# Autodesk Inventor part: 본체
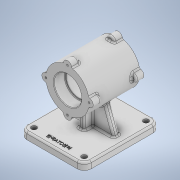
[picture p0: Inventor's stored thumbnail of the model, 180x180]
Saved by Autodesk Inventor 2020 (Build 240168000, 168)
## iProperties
Created: 2022-11
Part Number: 본체
Material: 일반
Document SubType Name: Modeling
Designer: owner
Density: 1 g/cm^3
Appearance: 기본값
Mass: 448.497 g
Surface Area: 803.898 cm^2
Volume: 448.497 cm^3
Author: owner
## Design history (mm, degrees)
sketch "스케치1"
  geometry: L1 (55, 65)-(-55, 65); L2 (-55, 65)-(-55, -65); L3 (-55, -65)-(55, -65); L4 (55, -65)-(55, 65); L5 (55, 65)-(-55, -65); L6 (-55, 65)-(55, -65); 1 further point
  constraints: 12 end point, 2 midpoint, 2 parallel, 1 horizontal, 1 perpendicular
  dimensions: "d0" = 110 distance of L3.end L2.end; "d1" = 130 distance of L2.end L1.end
extrude "돌출1" new body sketch "스케치1" distance "d2" = 12; taper "d3" = 0 deg
node "작업 평면1"
sketch "스케치6"
  geometry: L1 (0, 0)-(110, 0) reference; C1 r 37 at (55, 82); 2 further points
  constraints: 1 centre point, 1 midpoint, 1 vertical alignment
  dimensions: "d20" = 82 distance from line of L1 C1.centre; "d86" = 74 diameter of C1
extrude "돌출4" join sketch "스케치6" stored distance "d21" = 87; taper "d22" = 0 deg
sketch "스케치7"
  geometry: L1 (80.336, 55.036)-(96, 12); L2 (0, 12)-(110, 12) reference; L3 (110, 0)-(110, 12) reference; L4 (29.664, 55.036)-(14, 12); L5 (0, 0)-(0, 12) reference; A1 r 37 centre (55, 82) between (80.336, 55.036) and (29.664, 55.036) reference; 3 further points
  constraints: 4 end point, 2 point on circle
  dimensions: "d23" = 70 deg angle of L2 L1; "d24" = 0 distance from line of L2 L1.end; "d25" = 14 distance from line of L3 L1.end; "d26" = 70 deg angle of L2 L4; "d27" = 14 distance from line of L5 L4.end; "d28" = 0 distance from line of L2 L4.end
extrude "돌출5" join sketch "스케치7" stored distance "d29" = 10; taper "d30" = 0 deg
sketch "스케치9"
  geometry: L1 (14, 12)-(96, 12) reference; L2 (60, 52)-(50, 52); L3 (50, 52)-(50, 12); L4 (50, 12)-(60, 12); L5 (60, 12)-(60, 52); L6 (60, 52)-(50, 12); L7 (50, 52)-(60, 12); A1 r 37 centre (55, 82) between (29.664, 55.036) and (80.336, 55.036) reference; 5 further points
  constraints: 12 end point, 3 midpoint, 2 parallel, 1 horizontal, 1 perpendicular, 1 vertical alignment
  dimensions: "d31" = 10 distance of L4.end L3.end; "d32" = 40 distance of L3.end L2.end; "d33" = 0 distance between parallel lines of L4 L1
extrude "돌출6" join sketch "스케치9" stored distance "d34" = 40; taper "d35" = 0 deg
sketch "스케치10"
  geometry: C1 r 7 at (0, 37); 2 further points
  constraints: 2 vertical alignment, 1 centre point, 1 other
  dimensions: "d36" = 14 diameter of C1
extrude "돌출7" join sketch "스케치10" distance "d37" = 14; taper "d38" = 0 deg
sketch "스케치11"
  geometry: A1 r 7 centre (55, 119) between (61.969, 118.338) and (48.031, 118.338) reference; 2 further points
  constraints: 1 coincident
hole "구멍1" sketch "스케치11" at (55, 119) diameter "d39" = 3.242; stored, may be unused: countersink angle "d43" = 90 deg, drill point angle "d45" = 118 deg; dims "d40" = 8, "d41" = 4, "d42" = 2, "d44" = 11.8
fillet "모깎기4" dims "d76" = 3
fillet "모깎기5" dims "d77" = 3
sketch "스케치12"
  geometry: A1 r 37 centre (55, 82) between (48.031, 118.338) and (18.662, 88.969) reference; 2 further points
  constraints: 1 coincident
hole "구멍2" sketch "스케치12" at (55, 82) diameter "d49" = 47; stored, may be unused: countersink angle "d53" = 90 deg, drill point angle "d55" = 0 deg; dims "d50" = 8, "d51" = 4, "d52" = 2, "d54" = 19
sketch "스케치13"
  geometry: C1 r 23.5 at (0, 0) reference; 2 further points
  constraints: 1 coincident
hole "구멍3" sketch "스케치13" at (0, 0) diameter "d56" = 42; stored, may be unused: countersink angle "d60" = 90 deg, drill point angle "d62" = 0 deg; dims "d57" = 8, "d58" = 4, "d59" = 2, "d61" = 19
fillet "모깎기1" dims "d63" = 12
sketch "스케치14"
  geometry: A1 r 12 centre (-43, -53) between (-55, -53) and (-43, -65) reference; 2 further points
  constraints: 1 coincident
hole "구멍4" sketch "스케치14" at (-43, -53) diameter "d64" = 9; stored, may be unused: countersink angle "d68" = 90 deg, drill point angle "d70" = 0 deg; dims "d65" = 8, "d66" = 4, "d67" = 2, "d69" = 19
fillet "모깎기2" dims "d71" = 3
fillet "모깎기3" dims "d72" = 1
chamfer "모따기1" distance "d73" = 1; stored, may be unused: second distance "d74" = 2, angle "d75" = 45 deg
fillet "모깎기6" dims "d78" = 3
fillet "모깎기7" dims "d79" = 3
fillet "모깎기8" dims "d80" = 3
fillet "모깎기9" dims "d81" = 3
fillet "모깎기10" dims "d82" = 3
sketch "스케치15"
  geometry: L1 (-55, -53)-(-52, -53) reference; L2 (43, -62)-(-43, -62) reference; 3 further points
  constraints: 1 midpoint, 1 vertical alignment, 1 other
  dimensions: "d83" = 0 distance from line of point (0, -53) L1
feature "엠보싱1" sketch "스케치15" dims "d0" = 110, "d1" = 130, "d24" = 0, "d84" = 0.5, "d85" = 0
sketch "스케치16"
  geometry: 1 further point
node "솔리드1"
pattern_circular "원형 패턴1" dims angle "d47" = 360 deg
mirror "미러1"
mirror "미러2"
mirror "미러3"
feature "A9D066F2-1C7D-4E18-AEED-F7BC21143FA4" dims "d39" = 3.242, "d40" = 8, "d41" = 4, "d42" = 2, "d43" = 90 deg, "d44" = 11.8, "d45" = 118 deg
